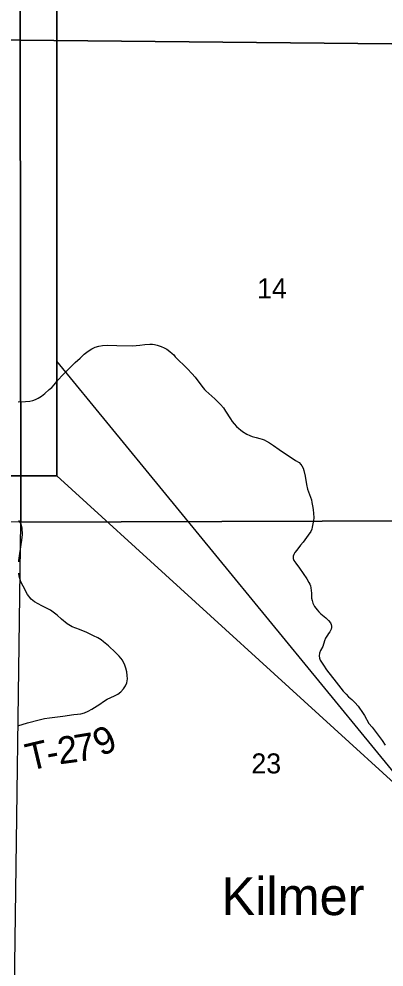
# Model space of a CAD drawing. Extents: x 0 to 34, y 0 to 22.
# Drawn here: x 4.406 to 5.171, y 17.465 to 19.45 of the extents above; entities that cross this region are included whole.
import ezdxf

# ---------------------------------------------------------------- set-up
doc = ezdxf.new("R2010")
doc.units = 0
for name, color, linetype in [('GM_X_Corporation', 7, 'Continuous'), ('GM_X_Section_Text', 7, 'Continuous'), ('GM_X_Township_Road', 7, 'Continuous'), ('GM_X_Township_Road_Text', 7, 'Continuous'), ('GM_X_Unincorporated_Text', 7, 'Continuous'), ('SH_Text', 7, 'Continuous')]:
    doc.layers.add(name, color=color, linetype=linetype)

msp = doc.modelspace()

# ---------------------------------------------------------------- linework, layer by layer
at = {"layer": 'GM_X_Corporation'}
for points in [[(3.3928, 20.4074), (4.4129, 20.4084), (4.4084, 19.4053), (3.384, 19.4149)], [(5.4711, 20.4076), (5.4696, 19.395), (4.4084, 19.4053), (4.4129, 20.4084)], [(3.384, 19.4149), (4.4084, 19.4053), (4.4097, 18.3961), (3.3747, 18.3998)], [(5.4696, 19.395), (5.4623, 18.3997), (4.4097, 18.3961), (4.4084, 19.4053)], [(4.4097, 18.3961), (5.4623, 18.3997), (5.4343, 17.4017), (4.3969, 17.419)]]:
    msp.add_lwpolyline(points, close=True, dxfattribs=at)
at = {"layer": 'GM_X_Township_Road'}
for points in [[(4.4042, 18.6479), (4.4196, 18.6486), (4.4288, 18.6495), (4.4348, 18.6508), (4.4406, 18.6527), (4.4464, 18.6559), (4.453, 18.6602), (4.4601, 18.6657), (4.4695, 18.6737), (4.4746, 18.6784), (4.4797, 18.6839), (4.4884, 18.6945), (4.4971, 18.7038), (4.5092, 18.716), (4.5239, 18.7304), (4.5341, 18.7399), (4.5429, 18.7479), (4.5508, 18.7541), (4.5586, 18.759), (4.5658, 18.7627), (4.5732, 18.7648), (4.581, 18.7662), (4.5924, 18.7668), (4.6111, 18.7658), (4.6442, 18.7652), (4.659, 18.7668), (4.67, 18.7679), (4.6803, 18.7686), (4.6855, 18.769), (4.69, 18.7685), (4.6958, 18.767), (4.7039, 18.7642), (4.7104, 18.761), (4.7155, 18.7583), (4.7224, 18.7537), (4.727, 18.7496), (4.7302, 18.7462), (4.7329, 18.7424), (4.759, 18.717), (4.7683, 18.7073), (4.775, 18.6996), (4.7852, 18.6868), (4.7916, 18.6777), (4.7944, 18.6739), (4.7973, 18.6709), (4.8164, 18.6542), (4.828, 18.6428), (4.8343, 18.6353), (4.839, 18.6284), (4.8491, 18.6128), (4.8529, 18.6071), (4.8567, 18.6019), (4.8616, 18.5967), (4.8664, 18.5922), (4.8701, 18.5893), (4.8745, 18.5861), (4.8834, 18.5807), (4.8893, 18.5776), (4.8948, 18.5756), (4.9027, 18.5732), (4.9103, 18.5713), (4.9152, 18.5701), (4.9197, 18.5684), (4.9246, 18.5659), (4.9307, 18.5623), (4.9392, 18.5564), (4.9508, 18.5485), (4.9644, 18.5392), (4.9739, 18.5329), (4.9856, 18.5256), (4.9928, 18.521), (4.9967, 18.5171), (4.9987, 18.5139), (5.0012, 18.5093), (5.003, 18.5044), (5.0056, 18.4926), (5.008, 18.4754), (5.0106, 18.4656), (5.0148, 18.4544), (5.0186, 18.4427), (5.0198, 18.4377), (5.0212, 18.4306), (5.0226, 18.4226), (5.0233, 18.4146), (5.0236, 18.4061), (5.023, 18.3988), (5.0219, 18.3927), (5.0204, 18.3858), (5.0192, 18.3816), (5.0172, 18.3769), (5.0121, 18.3688), (5.0013, 18.3543), (4.9961, 18.3481), (4.9878, 18.3374), (4.984, 18.3325), (4.9818, 18.3284), (4.9804, 18.3249), (4.9805, 18.3203), (4.982, 18.3162), (4.9858, 18.3105), (4.9937, 18.2999), (5.0089, 18.2776), (5.0135, 18.2701), (5.0154, 18.2662), (5.0167, 18.2626), (5.0176, 18.2585), (5.0184, 18.2534), (5.0186, 18.2477), (5.019, 18.2371), (5.02, 18.232), (5.0217, 18.2268), (5.0254, 18.2194), (5.0307, 18.2124), (5.0343, 18.2085), (5.0384, 18.2043), (5.0485, 18.196), (5.0541, 18.1906), (5.0583, 18.1857), (5.06, 18.1821), (5.0607, 18.1785), (5.0607, 18.1756), (5.0598, 18.172), (5.0569, 18.1665), (5.0547, 18.163), (5.0521, 18.1595), (5.0481, 18.1536), (5.0459, 18.1477), (5.0426, 18.1359), (5.0374, 18.1272), (5.0358, 18.1216), (5.035, 18.1163), (5.0354, 18.1117), (5.0372, 18.1076), (5.0443, 18.0966), (5.0505, 18.0872), (5.0703, 18.0612), (5.0854, 18.0424), (5.0912, 18.0358), (5.0964, 18.0307), (5.103, 18.0247), (5.1099, 18.0184), (5.1163, 18.0112), (5.1197, 18.0068), (5.1246, 18.0001), (5.1298, 17.9917), (5.1391, 17.9749), (5.1457, 17.967), (5.1672, 17.9392), (5.1732, 17.9292)], [(4.4057, 18.3132), (4.4061, 18.317), (4.4064, 18.3196), (4.4068, 18.3221), (4.407, 18.3243), (4.4073, 18.3265), (4.4077, 18.3308), (4.4123, 18.3584), (4.4136, 18.3703), (4.4128, 18.3837), (4.4103, 18.3925), (4.4058, 18.3998)], [(4.4036, 17.9698), (4.4236, 17.9761), (4.4486, 17.9824), (4.4592, 17.9849), (4.4702, 17.9867), (4.4981, 17.9903), (4.5211, 17.9932), (4.5287, 17.9939), (4.5359, 17.9948), (4.5436, 17.997), (4.551, 18.0002), (4.5586, 18.0045), (4.5644, 18.008), (4.5751, 18.0155), (4.5828, 18.0205), (4.5909, 18.0256), (4.6063, 18.0327), (4.6129, 18.0364), (4.6194, 18.0409), (4.625, 18.047), (4.6294, 18.0532), (4.6322, 18.06), (4.6335, 18.0679), (4.633, 18.0752), (4.6318, 18.0831), (4.6297, 18.0908), (4.6275, 18.0969), (4.6229, 18.1076), (4.6161, 18.1159), (4.6085, 18.1236), (4.5934, 18.1373), (4.5832, 18.1458), (4.5783, 18.1496), (4.5714, 18.1537), (4.5621, 18.1585), (4.5481, 18.1653), (4.5327, 18.1717), (4.5174, 18.1774), (4.5068, 18.1832), (4.4954, 18.1928), (4.4861, 18.2016), (4.472, 18.212), (4.4537, 18.2212), (4.4386, 18.2294), (4.4317, 18.2349), (4.4239, 18.245), (4.4148, 18.262), (4.4102, 18.2715), (4.4067, 18.2832), (4.4055, 18.2893)]]:
    msp.add_lwpolyline(points, dxfattribs=at)
at = {"layer": 'SH_Text'}
for points in [[(4.4854, 19.5924), (2.4095, 19.5924), (2.4095, 18.4935), (4.4854, 18.4935)], [(2.4095, 19.5924), (4.4854, 19.5924), (4.4854, 18.4935), (2.4095, 18.4935)], [(5.2622, 17.7854), (4.4854, 18.7335), (4.4854, 18.4935)]]:
    msp.add_lwpolyline(points, close=True, dxfattribs=at)

# ---------------------------------------------------------------- texts
at = {"layer": 'GM_X_Section_Text'}
for s, p in [('14', (4.9049, 18.8647)), ('23', (4.8929, 17.8702))]:
    msp.add_text(s, height=0.04186, rotation=0, dxfattribs=at).set_placement(p)
at = {"layer": 'GM_X_Township_Road_Text'}
for s, rotation, p in [('9', 25.6282, (4.5783, 17.9047)), ('2', 7.4891, (4.4903, 17.889)), ('7', 9.2522, (4.5269, 17.8938)), ('T', 13.3939, (4.4276, 17.8751)), ('-', 10.5353, (4.4682, 17.8848))]:
    msp.add_text(s, height=0.0568, rotation=rotation, dxfattribs=at).set_placement(p)
at = {"layer": 'GM_X_Unincorporated_Text'}
msp.add_text('Kilmer', height=0.07898, rotation=0, dxfattribs=at).set_placement((4.8304, 17.5735))

doc.saveas('drawing.dxf')
